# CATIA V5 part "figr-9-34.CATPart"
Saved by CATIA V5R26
Part number: Part1
Bounding box of the stored display mesh (mm): x -250 to 0, y -60 to 60, z 0 to 100
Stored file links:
  D:\_Deepak\CATIA\CATIA V5-6R2016_Deepak\Resources\Part files\Partfiles\c09_catia_v5_6r2016_prt\figr-9-34.CATPart
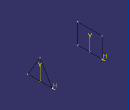
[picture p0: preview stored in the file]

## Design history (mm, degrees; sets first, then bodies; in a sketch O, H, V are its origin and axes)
Body1 (main body)
  Sketch1 on yz-plane, origin (0, 0, 0), H (0, 1, 0), V (0, 0, 1)
    point P1 (-60, 0)
    line L1 (-60, 0) -> (0, 100)
    point P2 (0, 100)
    line L2 (0, 100) -> (60, 0)
    point P3 (60, 0)
    line L3 (60, 0) -> (-60, 0)
    coincidence: P1 H, P2 V, P3 H
    horizontal: L3 H
    midpoint: O L3
  Sketch2, origin (-250, 0, 0), H (0, 1, 0), V (0, 0, 1)
    point P1 (-60, 0)
    line L1 (-60, 0) -> (60, 0)
    line L2 (60, 0) -> (60, 100)
    line L3 (60, 100) -> (-60, 100)
    line L4 (-60, 100) -> (-60, 0)
    coincidence: P1 H
    horizontal: L1 H, L3 H
    vertical: L2 V, L4 V
  Loft1: Sections (Sketch1; Sketch2), SectionCouplingPoints ({coupling CouplingPoints (vertex [element of Sketch1 | element of Sketch1]; vertex [element of Sketch2 | element of Sketch2])}; {coupling CouplingPoints (vertex [element of Sketch1 | element of Sketch1]; vertex [element of Sketch2 | element of Sketch2])}; {coupling CouplingPoints (vertex [element of Sketch1 | element of Sketch1]; vertex [element of Sketch2 | element of Sketch2])})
